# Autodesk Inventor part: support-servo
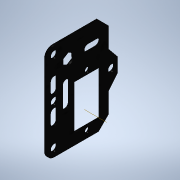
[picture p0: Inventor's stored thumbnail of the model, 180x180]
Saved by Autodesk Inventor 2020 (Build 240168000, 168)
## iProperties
Created: 2021-10
Part Number: support-servo
Material: Générique
Document SubType Name: Tôle
Designer: bruno
Density: 1 g/cm^3
Sheet Metal Rule: Par défaut_mm
Appearance: Noir
Author: bruno
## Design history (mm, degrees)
sketch "Esquisse1"
  geometry: L1 (4, 0)-(44, 0); L2 (48, -4)-(48, -26); L3 (0, -26)-(0, -4); L4 (24, 0)-(24, -30.702); L5 (33.07, -2.25)-(28.57, -2.25); L6 (28.57, -5.75)-(33.07, -5.75); L7 (14.93, -2.25)-(19.43, -2.25); L8 (19.43, -5.75)-(14.93, -5.75); L9 (27.3, -26.952)-(5.3, -26.952); L10 (5.3, -26.952)-(5.3, -13.952); L11 (5.3, -13.952)-(27.3, -13.952); L12 (27.3, -13.952)-(27.3, -26.952); L13 (5, -30.982)-(0, -26); L14 (43, -30.982)-(48, -26); L15 (1.955, -20.452)-(29.582, -20.452); L16 (27.3, -26.952)-(43, -26.952); L17 (40.295, -20.701)-(40.3, -25.201); L18 (36.8, -20.832)-(36.8, -25.202); L19 (36.8, -26.952)-(36.8, -29.253); L20 (23.989, -34.202)-(23.989, -35.452); L21 (23.989, -35.452)-(27.489, -35.452); L22 (27.489, -35.452)-(32.95, -30.982); L23 (20.489, -35.452)-(15.027, -30.982); L24 (23.989, -35.452)-(20.489, -35.452); L25 (38.55, -25.202)-(38.55, -1.172); L26 (37.014, -8.556)-(39.898, -8.448); L27 (39.898, -8.448)-(41.435, -10.892); L28 (41.435, -10.892)-(40.086, -13.444); L29 (40.086, -13.444)-(37.202, -13.552); L30 (37.202, -13.552)-(35.665, -11.108); L31 (35.665, -11.108)-(37.014, -8.556); L32 (43, -30.982)-(32.95, -30.982); L33 (15.027, -30.982)-(5, -30.982); L34 (28.75, -11.75)-(24, -11.75); L35 (28.75, -8.25)-(24, -8.25); L36 (19.25, -8.25)-(24, -8.25); L37 (19.25, -11.75)-(24, -11.75); C1 r 1.75 at (44, -4); C2 r 1.75 at (4, -4); C3 r 1.75 at (24, -4); C4 r 1.25 at (29.3, -20.452); C5 r 1.25 at (3.3, -20.452); A1 r 4 centre (44, -4) between (48, -4) and (44, 0); A2 r 4 centre (4, -4) between (4, 0) and (0, -4); A3 r 1.75 centre (33.07, -4) between (33.07, -5.75) and (33.07, -2.25); A4 r 1.75 centre (28.57, -4) between (28.57, -2.25) and (28.57, -5.75); A5 r 1.75 centre (14.93, -4) between (14.93, -2.25) and (14.93, -5.75); A6 r 1.75 centre (19.43, -4) between (19.43, -5.75) and (19.43, -2.25); A7 r 1.75 centre (38.55, -25.202) between (36.8, -25.202) and (40.3, -25.201); A8 r 1.75 centre (38.545, -20.702) between (40.295, -20.701) and (36.8, -20.832); A9 r 1.75 centre (24.005, -32.452) between (23.989, -34.202) and (24, -30.702); A10 r 1.75 centre (28.75, -10) between (28.75, -11.75) and (28.75, -8.25); A11 r 1.75 centre (19.25, -10) between (19.25, -8.25) and (19.25, -11.75); 5 further points
  constraints: 74 end point, 22 point on circle, 16 centre point, 13 point on line, 11 symmetric about line, 11 tangent, 6 parallel, 5 perpendicular, 4 horizontal, 4 vertical, 2 coincident, 1 equal length, 1 equal radius, 1 midpoint, 16 other
  dimensions: "d0" = 48 distance of point (48, -31) point (0, -31); "d1" = 31 distance of point (48, 0) point (48, -31); "d2" = 4 radius of A1; "d3" = 3.5 diameter of C1; "d4" = 3.5 diameter of C2; "d5" = 3.5 diameter of C3; "d6" = 3.5 diameter of A3; "d7" = 3.5 diameter of A4; "d8" = 4.57015 distance from line of A4.centre L4; "d9" = 4.5 distance of A3.centre A4.centre; "d10" = 22 distance between parallel lines of L10 L12; "d11" = 13 distance of L9.end L10.end; "d12" = 5.3 distance between parallel lines of L3 L10; "d14" = 5 distance of L13.start point (0, -31); "d15" = 5 distance of L3.start point (0, -31) (= d14); "d16" = 5 distance of L14.start point (48, -31) (= d14); "d17" = 5 distance of L2.end point (48, -31) (= d16); "d18" = 2.5 diameter of C4; "d19" = 2.5 diameter of C5; "d20" = 26 distance of C4.centre C5.centre; "d21" = 2 distance from line of L12 C4.centre; "d22" = 3.5 diameter of A7; "d23" = 3.5 diameter of A8; "d24" = 4.5 distance of A8.centre L25.start; "d25" = 9.5 distance from line of L19.end L12; "d26" = 3.5 diameter of A9; "d27" = 3.5 distance of L20.end L21.end; "d28" = 3 distance from line of L21 A9.centre; "d29" = 11 distance from line of L1 point (38.55, -11); "d30" = 5 distance between parallel lines of L29 L26; "d31" = 3.5 diameter of A10; "d32" = 6 vertical distance of A10.centre A3.centre; "d33" = 4.75 distance from line of A10.centre L4; "d39" = 12 distance from line of L15 A9.centre; "d40" = 6.5 distance between parallel lines of L15 L11
extrude "Extrusion1" new body sketch "Esquisse1" distance "d34" = 1; taper "d35" = 0 deg
sketch "Esquisse2"
  geometry: L1 (-4, 24)-(-29.935, 24); L2 (-26.952, 27.3)-(-26.952, 5.3) reference; L3 (-20.35, 11.745)-(-20.304, 38); L4 (0, 44)-(0, 4) reference; C1 r 1.75 at (-4, 24) reference; C2 r 1.75 at (-32.452, 24.005) reference; C3 r 2.909 at (-20.452, 11.5); 1 further point
  constraints: 4 end point, 1 centre point, 1 perpendicular
  dimensions: "d38" = 12.10247 horizontal distance of L3.start C2.centre (derived); "d41" = 12.5 distance from line of L1 C3.centre; "d42" = 12 horizontal distance of C3.centre C2.centre
node "Axe de construction1"
node "Solide1"
other parameters: "Epaisseur" = 0.5 (derived), "FacteurX" = 4.4, "RayonPli" = 0.5 (= Epaisseur), "LargeurGrugeage" = 0.5 (= Epaisseur), "ProfondeurGrugeage" = 0.25 (= 0.5 x Epaisseur), "TailleGrugeage" = 2 (= 4 x Epaisseur), "JeuJointure" = 0.01, "RestesMinimum" = 1 (= 2 x Epaisseur), "Rayondetransition" = 0.5 (= RayonPli), "TailleRayonJacobi" = 0.5 (= RayonPli), "TailleJeu" = 0.5 (= Epaisseur), "d13" = 4.2
